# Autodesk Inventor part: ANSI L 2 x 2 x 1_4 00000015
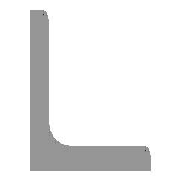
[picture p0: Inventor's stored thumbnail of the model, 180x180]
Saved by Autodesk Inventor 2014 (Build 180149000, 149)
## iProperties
IsCustomPart: 1
Created: 2007-02
Part Number: ANSI L 2 x 2 x 1_4 00000015
Material: Steel, Mild
Document SubType Name: Modeling
Standard: AISC
Designer: Autodesk, Inc.
Size Designation: L 2 x 2 x 1/4
Stock Number: L 2 x 2 x 1/4
Density: 7.86 g/cm^3
Description: Angle Steel
Standards Organization: ANSI
Language: en-US
Categories: <MemberInstance><Categories><Category DisplayName="Structural Shapes" InternalName="089c4875-fa83-4c05-b084-43b9cc11f5ed" Mnemonic="GRDR"><CategoryParameter Dis
Mass: 1645.44 g
Surface Area: 694.442 cm^2
Volume: 209.344 cm^3
Appearance: Steel
_FrameMemberDoc: Frame Member File
_Version: 15.0.0
_CCFamilyMember: 11
_CCFamilyDisplayName: ANSI L (Equal angles) - Angle Steel
G_L: 14.750 in
G_W: 2.000 in
G_H: 2.000 in
+0C829B48-3858-41F8-B33C-9FF71A575EB4+CUTDETAIL1: Miter 45.00 deg
+1B0D5935-5D52-4120-8208-152CEE6E40CF+CUTDETAIL2: Miter 45.00 deg
Author: Autodesk, Inc.
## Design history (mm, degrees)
node "Start plane"
node "End plane"
sketch "Sketch"
  geometry: L1 (50.8, 0)-(0, 0); L2 (0, 0)-(0, 50.8); L3 (0, 50.8)-(3.302, 50.8); L4 (6.35, 47.752)-(6.35, 12.7); L5 (12.7, 6.35)-(47.752, 6.35); L6 (50.8, 3.302)-(50.8, 0); L7 (0, -11.041)-(0, 31.538); L8 (-11.041, 0)-(31.538, 0); L9 (0, 63.926)-(0, -23.536) reference; L10 (-23.536, 0)-(63.926, 0) reference; A1 r 6.35 centre (12.7, 12.7) between (6.35, 12.7) and (12.7, 6.35); A2 r 3.048 centre (3.302, 47.752) between (6.35, 47.752) and (3.302, 50.8); A3 r 3.048 centre (47.752, 3.302) between (50.8, 3.302) and (47.752, 6.35); 3 further points
  constraints: 16 end point, 6 point on circle, 6 point on line, 6 tangent, 4 parallel, 3 centre point, 2 collinear, 1 equal radius, 1 horizontal, 1 perpendicular
  dimensions: "d0" = 50.8 distance between parallel lines of L6 L2 (= G_H); "d1" = 50.8 distance between parallel lines of L3 L1 (= G_H); "d2" = 6.35 distance between parallel lines of L2 L4 (= G_T); "d3" = 6.35 distance between parallel lines of L1 L5 (= G_T); "d10" = 0 distance between parallel lines of L7 L2 (computed from ex); "d11" = 0 distance between parallel lines of L8 L1 (computed from d10); "d14" = 6.35 radius of A1 (= G_IR); "d15" = 3.048 radius of A2 (= G_ER)
extrude "Body" new body sketch "Sketch" stored distance "d4" = 374.65 (= G_L); taper "d5" = 0 deg
node "Driven Length"
  sketch "Sketch4"
    geometry: L1 (0, 0)-(10, 0) reference
    constraints: 2 end point, 1 horizontal
  workplane "Work Plane5"
  sketch "Sketch5"
    geometry: L1 (-2, 0)-(12, 0) reference; L2 (-2, 374.65)-(12, 374.65) reference
    dimensions: "d19" = 374.65 distance between parallel lines of L1 L2 (derived)
workplane "Work Plane3"
split "Split1"
workplane "Work Plane4"
split "Split2"
sketch "Sketch3"
  geometry: L1 (374.65, 0)-(323.85, 50.8) reference; C1 r 8.331 at (34.925, 38.1) reference; A1 r 8.331 centre (339.725, 38.1) between (343.811, 30.839) and (332.464, 42.186) reference; A2 r 8.331 centre (339.725, 38.1) between (332.464, 42.186) and (343.811, 30.839) reference
  constraints: 2 centre point, 4 other
extrude "Extrusion2" cut sketch "Sketch3" stored distance "d16" = 25.4; taper "d17" = 0 deg
body "Solid1"
node "Reference1"
other parameters: "G_H" = 50.8 [user parameter; used in 2 equation terms], "G_T" = 6.35 [user parameter; used in 2 equation terms], "G_ER" = 3.048 [user parameter; used in 1 equation term], "G_IR" = 6.35 [user parameter; used in 1 equation term], "G_L" = 374.65 (= d19) [user parameter; used in 1 equation term], "ex" = 0 [user parameter; used in 1 equation term], "G_OFFSET_START" = 0 [user parameter; used in 1 equation term], "G_OFFSET_END" = 0 [user parameter; used in 1 equation term], "d12" = 0 (computed from G_OFFSET_START), "d13" = 374.65 (= G_OFFSET_END + B_L), "B_L" = 374.65 [user parameter; used in 1 equation term], "d18" = 90 deg
